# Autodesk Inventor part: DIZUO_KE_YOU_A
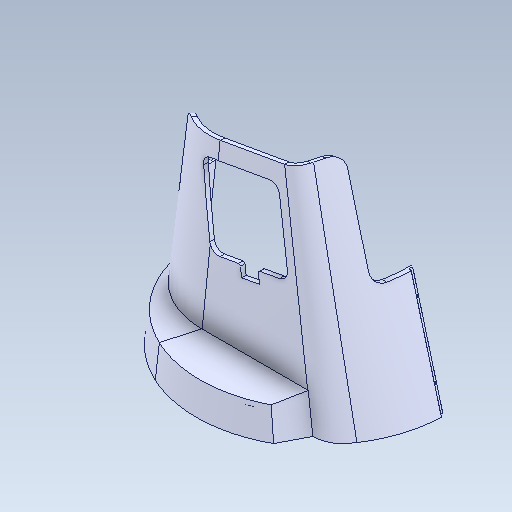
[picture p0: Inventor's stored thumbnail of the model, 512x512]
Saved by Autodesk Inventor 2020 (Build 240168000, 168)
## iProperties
Created: 2017-09
Part Number: DIZUO_KE_YOU_A
Material: Générique
Document SubType Name: Modeling
Designer: bruno
Density: 1 g/cm^3
Appearance: Par défaut
Author: bruno
Sending System: SolidWorks 2016
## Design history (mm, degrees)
feature "Importée1"
node "Solide1"
